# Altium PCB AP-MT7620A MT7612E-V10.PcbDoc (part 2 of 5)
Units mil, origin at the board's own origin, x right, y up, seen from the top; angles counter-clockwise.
Board outline 4645.67 x 3740.16 mil, 4 copper layers (Top, Inner Layer 2, Inner Layer 3, Bottom), stack 35.4 mil thick; 603 components, 409 nets, 1850 pads, 2004 vias.
Unrouted connection lines stored in the file: 90.
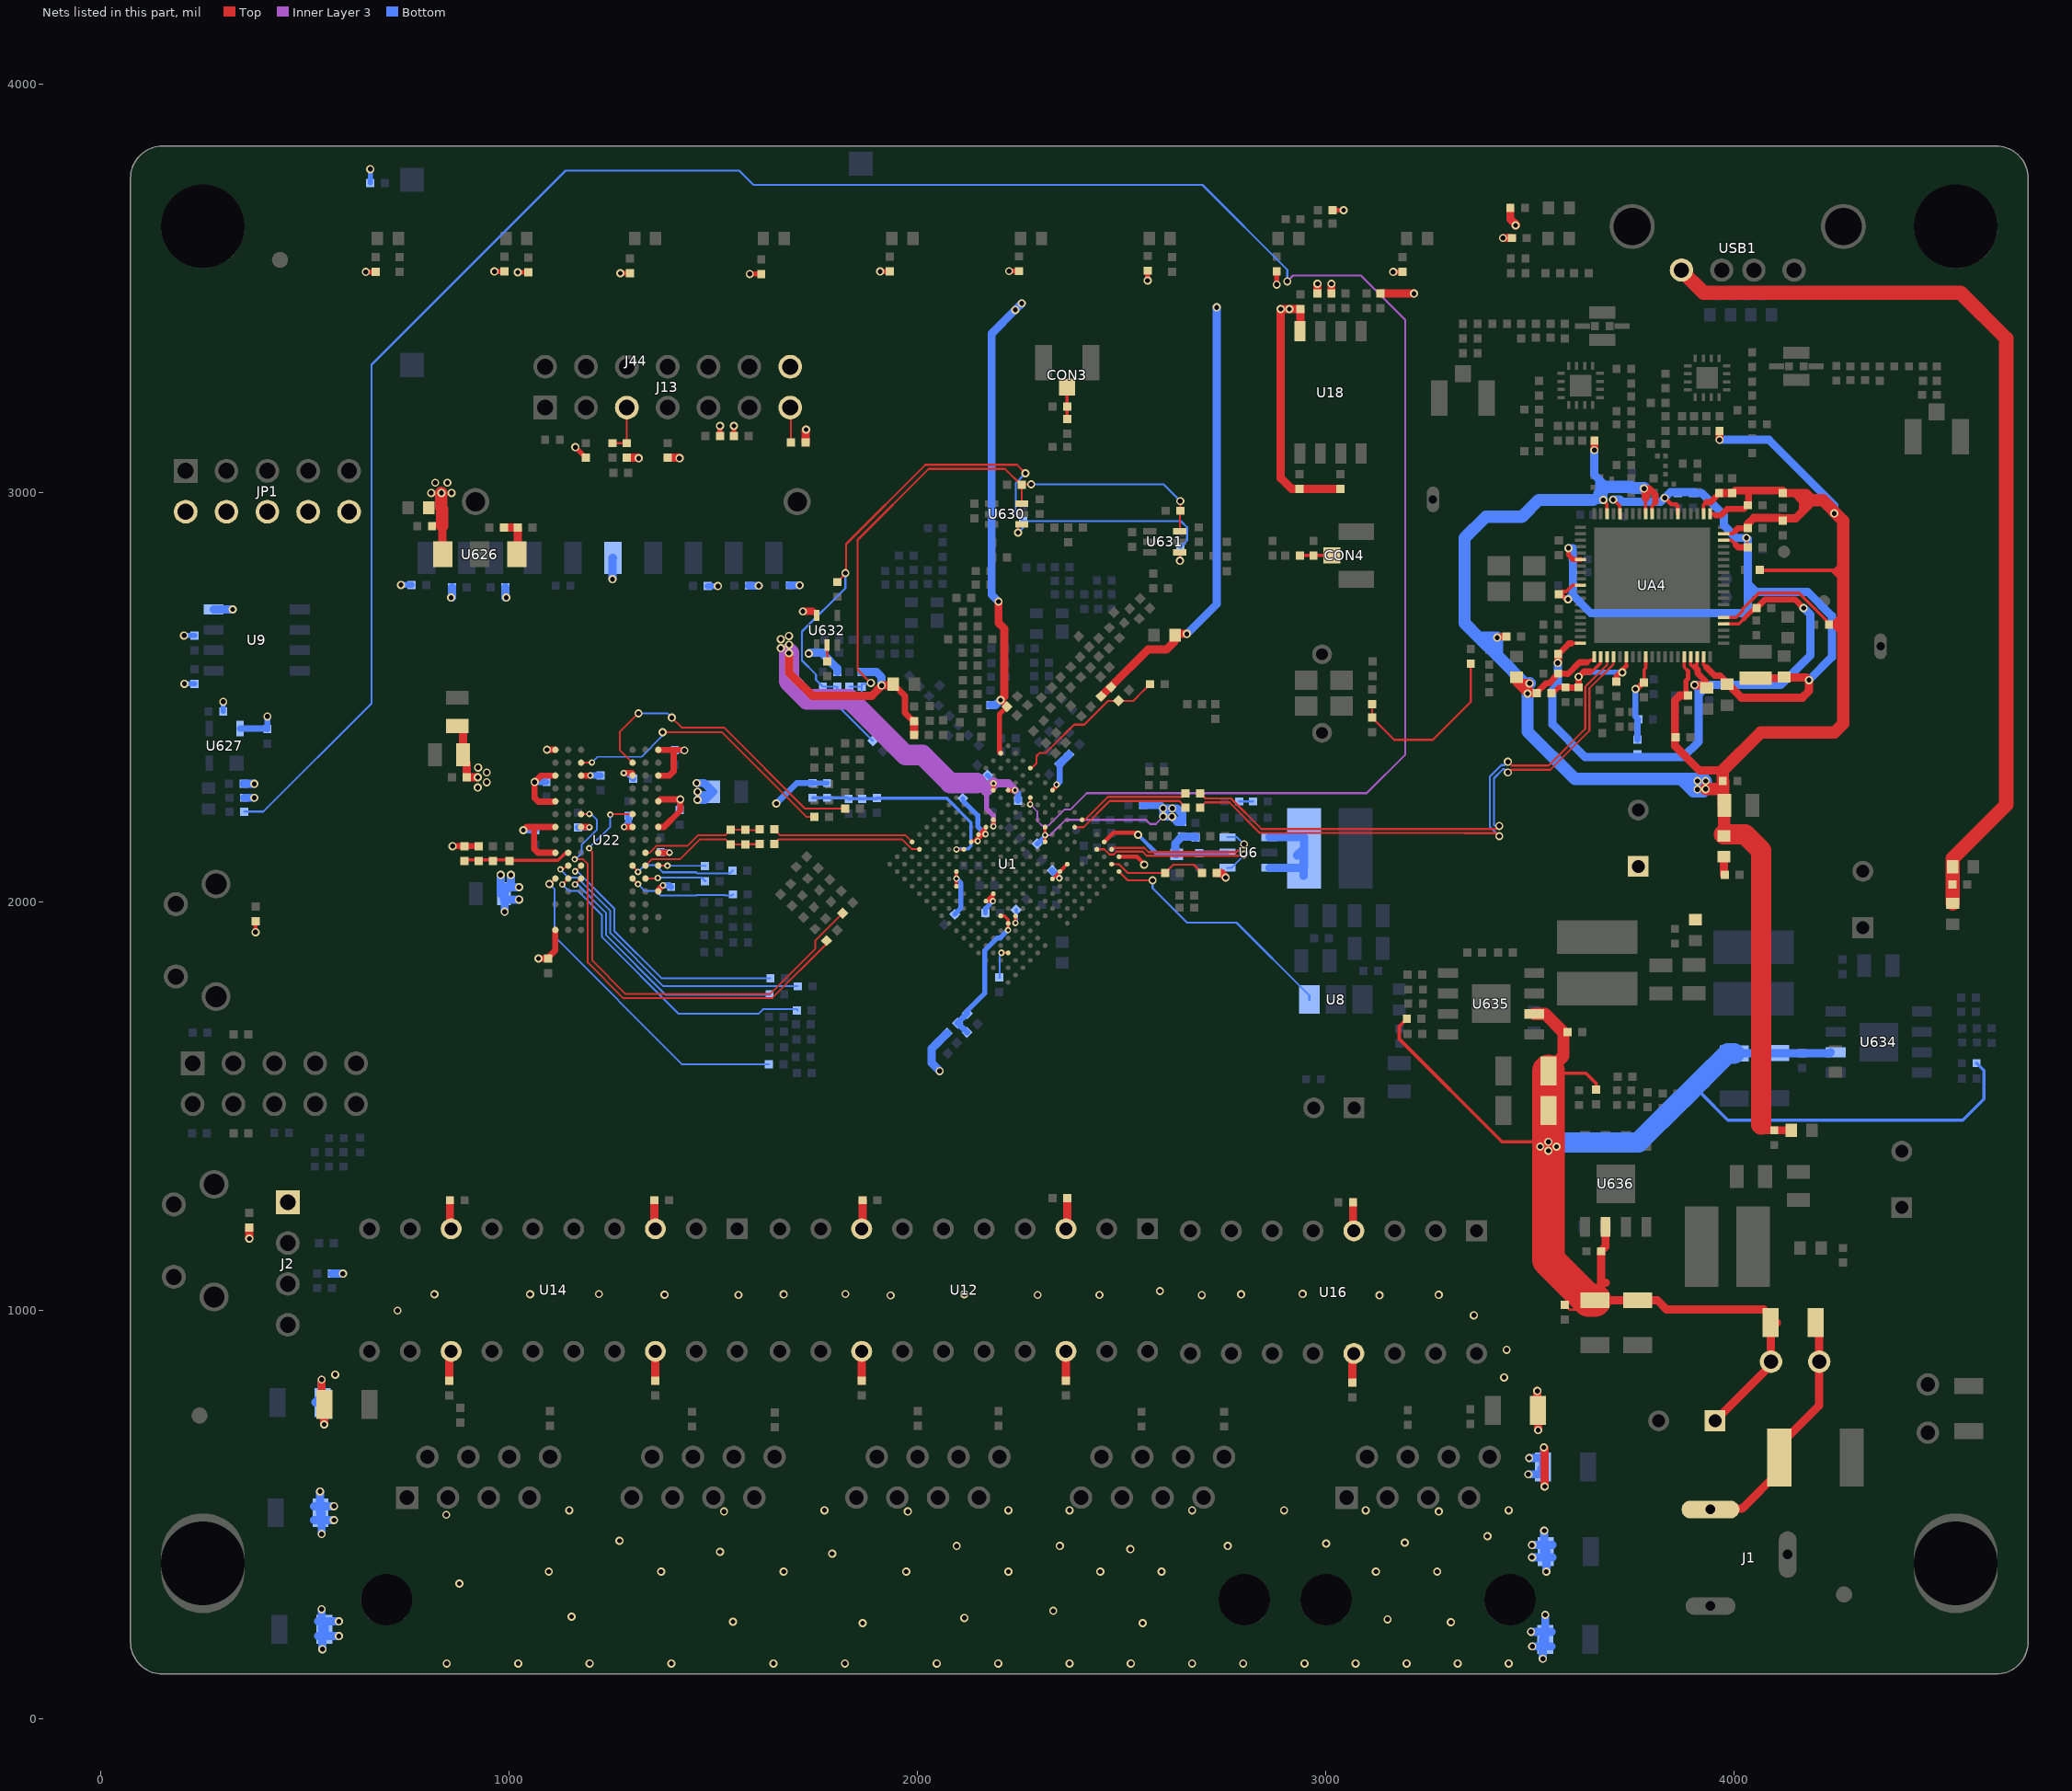
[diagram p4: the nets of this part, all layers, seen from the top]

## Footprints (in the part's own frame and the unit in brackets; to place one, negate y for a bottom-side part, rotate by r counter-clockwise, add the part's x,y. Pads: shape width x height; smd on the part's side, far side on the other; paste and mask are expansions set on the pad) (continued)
SHIELDING$2F$MPCIE$2F$2H$2F$T2 [mil]
  oval 30x62.99 hole 20 slot 53.15 at 90 deg: 1(-547.86,235.76) 2(547.86,-123.96)
  Top region: 220,279.5 220,311 377.48,311 377.48,279.5 220,279.5
  Top region: 405.02,311.02 405.02,279.53 531,279.53 531,-311.02 562.5,-311.02 562.5,311.02 405.02,311.02
  Top region: 273.5,-310.5 273.5,-279 430.98,-279 430.98,-310.5 273.5,-310.5
  Top region: -376,279.5 -376,311 -257.48,311 -257.48,279.5 -376,279.5
  Top region: -404.53,311.02 -562.99,311.02 -562.99,-310.04 -531.5,-310.04 -531.5,279.53 -404.53,279.53 -404.53,311.02
  Top region: -408,-311 -408,-279.5 -250.52,-279.5 -250.52,-311 -408,-311
SKY85601 [mm]
  rect 0.2x0.475 smd mask+0.05: 1(-0.75,-1.212) 2(-0.25,-1.212) 3(0.25,-1.212) 4(0.75,-1.212) 9(0.75,1.212) 10(0.25,1.212) 11(-0.25,1.212) 12(-0.75,1.212)
  rect 0.475x0.2 smd mask+0.05: 5(1.212,-0.75) 6(1.212,-0.25) 7(1.212,0.25) 8(1.212,0.75) 13(-1.212,0.75) 14(-1.212,0.25) 15(-1.212,-0.25) 16(-1.212,-0.75)
  rect 1.35x1.35 smd mask-0.05: 17(0,0)
  silkscreen extent -1.58,-1.58 1.33,1.33
SOIC8$2F$SMD$2F$P1.27$2F$AT24C04B-08B [mm]
  rect 0.61x1.235 smd: 1(-1.905,-2.68) 2(-0.635,-2.68) 3(0.635,-2.68) 4(1.905,-2.68) 5(1.905,2.68) 6(0.635,2.68) 7(-0.635,2.68) 8(-1.905,2.68)
  silkscreen extent -2.97,-2.49 2.5,2
SOIC8$2F$SMD$2F$P1.27$2F$AT26DF321 [mm]
  rect 0.68x1.25 smd: 1(-1.905,-3.805) 2(-0.635,-3.805) 3(0.635,-3.805) 4(1.905,-3.805) 5(1.905,3.805) 6(0.635,3.805) 7(-0.635,3.805) 8(-1.905,3.805)
  silkscreen extent -3.13,-3.17 2.73,2.75
SOP8$2F$SMD$2F$P1.27$2F$IT7653 [mm]
  rect 0.62x1.235 smd: 1(-1.905,-2.682) 2(-0.635,-2.682) 3(0.635,-2.682) 4(1.905,-2.682) 5(1.905,2.682) 6(0.635,2.682) 7(-0.635,2.682) 8(-1.905,2.682)
  rect 2.41x2.41 smd: 9(0,0)
  Top region: -1.65,1.205 1.65,1.205 1.65,-1.205 -1.65,-1.205 -1.65,1.205
  silkscreen extent -2.85,-2.38 2.5,2
SOT89$2F$SMD [mil]
  rect 50x70 smd: 1(-65,0) 2(0,0) 3(65,0)
  Top region: 25,-35 25,50 50,75 50,150 35,165 -35,165 -50,150 -50,75 -25,50 -25,-35 25,-35
  silkscreen extent -100,-45 100,175
SOT223-3$2F$SMD$2F$P2.3$2F$AX1007 [mm]
  rect 1.2x1.6 smd: 1(-2.3,-3.2) 2(0,-3.2) 3(2.3,-3.2)
  Top region: -1.65,4.15 1.65,4.15 1.65,2.25 -1.65,2.25 -1.65,4.15
  silkscreen extent -3.65,-2.15 3.4,1.9
SOT-23-6$2F$SMD$2F$P0.95$2F$APM2701AC [mm]
  rect 0.5x1 smd: 1(-0.95,-1.3) 2(0,-1.3) 3(0.95,-1.3) 4(0.95,1.3) 5(0,1.3) 6(-0.95,1.3)
  silkscreen extent -1.9,-1.25 1.65,1
SOT-143$2F$SMD$2F$G693 [mm]
  rect 0.89x0.95 smd: 1(-0.76,-1.075)
  rect 0.46x0.95 smd: 2(0.96,-1.075) 3(0.96,1.075) 4(-0.96,1.075)
  silkscreen extent -1.92,-1.1 1.62,0.8
SOT-353 [mm]
  rect 0.35x0.7 smd: 1(-0.65,-0.921) 3(0.65,-0.921) 4(0.65,0.921) 5(-0.65,0.921)
  rect 0.3x0.7 smd: 2(0,-0.921)
  silkscreen extent -1.09,-0.38 1.09,0.71
SW$2F$4P$2F$DIP$2F$TS02-CN-PF [mm]
  round 1.5 hole 1: 1(-2.25,0) 2(2.25,0)
  round 1.8 hole 1.3: 3(-3.5,2.5) 4(3.5,2.5)
  silkscreen extent -3.75,-5.85 3.75,4.05
TP30MIL [mil]
  round 30 smd: 1(0,0)
  silkscreen extent -20,-20 20,20
TRANSFORMER$2F$16P$2F$DIP$2F$HN1674CG [mm]
  rect 1.3x1.3 / inner round 1.3 / far side round 1.3 hole 0.8: 1(-8.9,-3.81)
  round 1.3 hole 0.8: 2(-6.35,-3.81) 3(-3.81,-3.81) 4(-1.27,-3.81) 5(1.27,-3.81) 6(3.81,-3.81) 7(6.35,-3.81) 8(8.9,-3.81) 9(8.9,3.81) 10(6.35,3.81) 11(3.81,3.81) 12(1.27,3.81) 13(-1.27,3.81) 14(-3.81,3.81) 15(-6.35,3.81) 16(-8.9,3.81)
  silkscreen extent -10.82,-5.61 10.2,5
TRANSFORMER$2F$20P$2F$DIP$2F$HN2066CG [mm]
  rect 1.3x1.3 / inner round 1.3 / far side round 1.3 hole 0.8: 1(-11.43,-3.81)
  round 1.3 hole 0.8: 2(-8.89,-3.81) 3(-6.35,-3.81) 4(-3.81,-3.81) 5(-1.27,-3.81) 6(1.27,-3.81) 7(3.81,-3.81) 8(6.35,-3.81) 9(8.89,-3.81) 10(11.43,-3.81) 11(11.43,3.81) 12(8.89,3.81) 13(6.35,3.81) 14(3.81,3.81) 15(1.27,3.81) 16(-1.27,3.81) 17(-3.81,3.81) 18(-6.35,3.81) 19(-8.89,3.81) 20(-11.43,3.81)
  silkscreen extent -13.34,-5.81 12.7,5.1
TSON6$2F$SMD$2F$P0.65$2F$UPG2179TB [mm]
  rect 0.4x0.825 smd: 1(-0.65,-0.937) 2(0,-0.937) 3(0.65,-0.937) 4(0.65,0.937) 5(0,0.937) 6(-0.65,0.937)
  silkscreen extent -1.36,-0.97 1.15,0.72
USB$2F$4P$2F$DIP$2F$ATOM$2F$A [mm]
  round 1.45 hole 0.95: 1(3.5,0) 2(1,0) 3(-1,0) 4(-3.5,0)
  round 2.8 hole 2.3: 5(-6.57,-2.71) 6(6.57,-2.71)
  silkscreen extent -7.3,-13.09 7.3,1.21
VARISTOR$2F$SMD$2F$TVM5B150L103RY [mm]
  rect 1.5x3.6 smd: 1(-2.25,0) 2(2.25,0)
  silkscreen extent -1.35,-1.8 1.35,1.8
WBGA84$2F$SMD$2F$P0.8$2F$W9751G6IB [mm]
  round 0.4 smd: A1(-5.6,-3.2) A2(-5.6,-2.4) A3(-5.6,-1.6) A7(-5.6,1.6) A8(-5.6,2.4) A9(-5.6,3.2) B1(-4.8,-3.2) B2(-4.8,-2.4) B3(-4.8,-1.6) B7(-4.8,1.6) B8(-4.8,2.4) B9(-4.8,3.2) C1(-4,-3.2) C2(-4,-2.4) C3(-4,-1.6) C7(-4,1.6) C8(-4,2.4) C9(-4,3.2) D1(-3.2,-3.2) D2(-3.2,-2.4) D3(-3.2,-1.6) D7(-3.2,1.6) D8(-3.2,2.4) D9(-3.2,3.2) E1(-2.4,-3.2) E2(-2.4,-2.4) E3(-2.4,-1.6) E7(-2.4,1.6) E8(-2.4,2.4) E9(-2.4,3.2) F1(-1.6,-3.2) F2(-1.6,-2.4) F3(-1.6,-1.6) F7(-1.6,1.6) F8(-1.6,2.4) F9(-1.6,3.2) G1(-0.8,-3.2) G2(-0.8,-2.4) G3(-0.8,-1.6) G7(-0.8,1.6) G8(-0.8,2.4) G9(-0.8,3.2) H1(0,-3.2) H2(0,-2.4) H3(0,-1.6) H7(0,1.6) H8(0,2.4) H9(0,3.2) J1(0.8,-3.2) J2(0.8,-2.4) J3(0.8,-1.6) J7(0.8,1.6) J8(0.8,2.4) J9(0.8,3.2) K2(1.6,-2.4) K3(1.6,-1.6) K7(1.6,1.6) K8(1.6,2.4) K9(1.6,3.2) L1(2.4,-3.2) L2(2.4,-2.4) L3(2.4,-1.6) L7(2.4,1.6) L8(2.4,2.4) M2(3.2,-2.4) M3(3.2,-1.6) M7(3.2,1.6) M8(3.2,2.4) M9(3.2,3.2) N1(4,-3.2) N2(4,-2.4) N3(4,-1.6) N7(4,1.6) N8(4,2.4) P2(4.8,-2.4) P3(4.8,-1.6) P7(4.8,1.6) P8(4.8,2.4) P9(4.8,3.2) R1(5.6,-3.2) R2(5.6,-2.4) R3(5.6,-1.6) R7(5.6,1.6) R8(5.6,2.4)
  silkscreen extent -6.85,-5.5 6.85,5.5

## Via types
v1: diameter 20, hole 12, Top to Bottom, 1824 vias
v2: diameter 16, hole 8, Top to Bottom, 180 vias

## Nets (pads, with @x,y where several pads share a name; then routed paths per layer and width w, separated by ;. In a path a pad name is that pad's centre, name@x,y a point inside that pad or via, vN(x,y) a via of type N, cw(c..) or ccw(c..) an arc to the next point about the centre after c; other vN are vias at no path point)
1.8VD: C73.1 C75.1 C76.1 C124.1 C128.1 C129.1 C130.1 C131.1 C132.1 C133.1 C134.1 C135.1 C136.1 C138.1 C139.1 C140.1 C820.1 C965.1 C966.1 R350.1 R812.1 R900.2 U1.H5 U1.J5 U1.K5 U1.N6 U1.P7 U22.A1 U22.A9 U22.C1 U22.C3 U22.C7 U22.C9 U22.E1 U22.E9 U22.G1 U22.G3 U22.G7 U22.G9 U22.J1 U22.J9 U22.M9 U22.R1 | length 2346.9
  Top w8: U1.P7@2095.83,2037.21 U1.N6@2095.83,2073.4 ; U1.K5@2132.02,2145.79 2134.24,2148 2139.12,2148 ; v2(2167,2165) v2@2165.21,2166.79 ; U1.H5@2168.21,2181.98 U1.H5@2165.72,2179.49 ; 2139.12,2148 U1.J5@2150.12,2159 ; 2139.12,2148 v2@2146.42,2148 ; v2@2146.42,2148 v2@2148.77,2150.35 ; v2@2146.42,2148 v2(2148,2148) v2@2148.77,2150.35 ; v2@2148.77,2150.35 v2@2150.12,2151.7 ; v2@2150.12,2151.7 v2@2150.82,2152.39 ; v2@2150.12,2151.7 U1.J5@2150.12,2159 ; U1.J5@2150.12,2159 U1.J5@2150.12,2163.88 2159.12,2172.88 ; v2@2150.82,2152.39 v2@2165.21,2166.79 ; v2@2150.82,2152.39 2150.82,2155.61 v2@2163.61,2168.39 ; 2159.12,2172.88 U1.H5@2165.72,2179.49 ; 2159.12,2172.88 v2@2163.61,2168.39 ; v2@2163.61,2168.39 v2@2165.21,2170 ; v2@2163.61,2168.39 v2@2165.21,2166.79 ; v2@2165.21,2166.79 v2@2165.21,2170 ; v2@2165.21,2170 2165.72,2170.51 U1.H5@2165.72,2179.49
  Top w15: v1(862.5,2135.5) C124.1@891.5,2135.5 R350.1@926.5,2135.5 ; v1(1035.5,2174.5) 1043.31,2182.31 1062.32,2182.31 ; v1(1072.6,1860.56) 1094.01,1860.56 C132.1@1094.07,1860.5 ; v1(1093.5,2371.5) 1113.86,2371.5 U22.A1@1114.07,2371.29 ; C132.1@1096.5,1860.5 C132.1@1094.07,1860.5 ; U22.R1@1114.07,1930.35 1114.07,1880.5 C132.1@1094.07,1860.5 ; U22.J1@1114.07,2119.32 1071.5,2119.32 1062.32,2128.5 1062.32,2182.31 ; U22.G1@1114.07,2182.31 1062.32,2182.31 ; U22.E1@1114.07,2245.31 1113.26,2244.5 1072.5,2244.5 1063.5,2253.5 v1(1063.5,2292.5) 1079.3,2308.3 U22.C1@1114.07,2308.3 ; U22.G3@1177.06,2182.31 1196.69,2182.31 v2(1197.5,2181.5) ; U22.C3@1177.06,2308.3 1199.4,2308.3 v2(1199.7,2308.6) ; v2(1281.5,2314.5) 1301.5,2314.5 1303.05,2312.95 U22.C7@1303.05,2308.3 ; v2(1282.5,2182.5) 1302.86,2182.5 U22.G7@1303.05,2182.31 ; U22.M9@1366.04,2024.83 1366.04,2028.04 v2(1377.5,2039.5) ; U22.J9@1366.04,2119.32 1393.32,2119.32 v2(1393.5,2119.5) ; U22.G9@1366.04,2182.31 1379.95,2182.31 1420,2222.37 v1(1420,2250) 1370.73,2250 U22.E9@1366.04,2245.31 ; U22.C9@1366.04,2308.3 1393.5,2308.3 1403.5,2318.3 1403.5,2371.29 ; U22.A9@1366.04,2370.5 U22.A9@1366.04,2371.29 1403.5,2371.29 ; v1(1430,2370) 1430,2371.29 1403.5,2371.29
  Top w20: R900.2@874,2429.55 888.45,2429.55 C965.1@888.45,2359 888.45,2348 897,2339.45 C966.1@897,2304 v1(924,2304)
  Bottom w12: R812.1@1744,2290 C820.1@1779,2290 ; C76.1@2091.73,1968.73 2107,1984 2107,2045 v2(2096,2056) ; C75.1@2111.73,2252.27 2111.73,2247 2148,2211 2148,2184 v2(2167,2165)
  Bottom w15: v1(1035.5,2174.5) C129.1@1064.5,2174.5 ; v1(1063.5,2292.5) C138.1@1092.5,2292.5 ; C131.1@1169.5,2181.5 v2(1197.5,2181.5) ; v2(1199.7,2308.6) 1224.4,2308.6 C140.1@1224.5,2308.5 ; v2(1281.5,2314.5) 1290.5,2314.5 C128.1@1304.5,2300.5 ; v2(1282.5,2182.5) 1293.5,2193.5 C133.1@1293.5,2209.5 ; C139.1@1371.5,2120.5 1392.5,2120.5 v2(1393.5,2119.5) ; v2(1377.5,2039.5) 1393.5,2039.5 C130.1@1397.5,2035.5 ; C134.1@1406.5,2370.5 1406.5,2370 v1(1430,2370) ; C135.1@1418.5,2224.5 1420,2224.5 v1(1420,2250) ; C136.1@1500.05,2268.5 C136.1@1500.5,2268.05 ; v1(1655,2240) 1705,2290 R812.1@1744,2290
  Bottom w20: v1(980,2065) 980,2019 C73.1@988.45,2019 ; v1(990,1975) C73.1@990,2005 ; v1(1005,2065) 1005,2040 C73.1@1000,2035 ; v1(1025,2005) C73.1@990,2005 ; v1(1025,2035) C73.1@1000,2035 ; v1(1460,2290) 1478.55,2290 C136.1@1500.05,2268.5 C136.1@1500,2268.5 ; v1(1461.87,2248.71) 1480.21,2248.71 C136.1@1500,2268.5 ; v1(1462.24,2268.71) 1462.24,2268.27 1470.51,2260 1490,2260 1498.5,2268.5 C136.1@1500,2268.5 ; C73.1@988.45,2019 988.45,2005 C73.1@990,2005 ; C73.1@988.45,2019 990,2019 C73.1@990,2005 ; C73.1@988.45,2019 C73.1@988.45,2023.45 ; C73.1@988.45,2023.45 C73.1@1000,2035 ; C73.1@988.45,2023.45 988.45,2035 C73.1@1000,2035
  other v1: 924,2279 946,2292 946,2316 925,2328
3.3V: C925.1 C926.1 C952.1 CA41.1 CA42.1 CA43.1 CA45.1 CA52.1 CA53.1 CA55.1 CA56.1 CA57.1 CA58.1 CA63.1 CA64.1 CA74.1 L645.2 L648.2 R162.1 R164.1 RA7.2 RA10.1 RA18.2 RA21.2 UA4.20 UA4.34 UA4.43 UA4.56 UA4.58 UA4.59 UA4.67 UA4.68 UA4.74 | length 6771.4
  Top w5: CA64.1@3855,2402 CA64.1@3857,2402 ; RA21.2@4232,2678 4247,2678
  Top w8: 3639.38,2585.51 3642.04,2585.51 3646.94,2590.41 3657.27,2590.41 UA4.20@3657.27,2598.8 ; v1(3679.62,2982.87) 3678.86,2982.12 3688.76,2972.22 3688.76,2958.65 UA4.74@3688.76,2949.2 ; UA4.68@3783.25,2949.2 3783.25,2983.28 3783.37,2983.4 3783.37,2988.13 ; UA4.67@3799,2949.2 3799,2968.16 3807.14,2976.3 ; UA4.34@3877.74,2598.8 3877.74,2573.31 3886.86,2564.19 ; UA4.59@3924.98,2949.2 3924.98,2970.63 3931.71,2977.36 ; UA4.58@3940.73,2949.2 3949.34,2949.2 3953.75,2944.79 ; UA4.43@3974.2,2695.26 4004.74,2695.26 4020.71,2711.23 4020.71,2715.27 4060.37,2754.93 4158.88,2754.93 4232,2681.82 RA21.2@4232,2678 ; UA4.56@3974.2,2899.98 3974.2,2900.57 3996.19,2900.57 4003.03,2907.41
  Top w10: RA10.1@4062.88,2812 4062.88,2810.68 4240,2810.68 ; 4267,2783.68 4240,2810.68 ; 4267,2810 4266.32,2810.68 4246.33,2810.68 ; 4267,2831.35 4246.33,2810.68 ; 4240,2810.68 4246.33,2810.68
  Top w12: CA63.1@3882,2504 3882,2540.55 3886.86,2545.41 3886.86,2564.19
  Top w15: RA18.2@3517,2511.68 3539.32,2534 3546.68,2534 3558.2,2545.52 3558.2,2546.91 3567.24,2555.95 3567.24,2558 CA74.1@3569,2558 3586.79,2558 3590.33,2556.53 3592.7,2556.53 3621.68,2585.51 3639.38,2585.51 ; 3803,3000 3807.14,2995.86 3807.14,2976.3 ; 3931.71,2977.36 3942.05,2977.36 3963.84,2999.16 CA53.1@3963.84,3000 ; 3953.75,2944.79 3966.56,2944.79 3982.34,2960.57 4023.57,2960.57 CA56.1@4033,2970 ; 4003.03,2907.41 4009.62,2914 CA58.1@4033,2914
  Top w16: v1(3420,2646) 3420,2647.98 3442.69,2647.98 RA7.2@3442.69,2648.48 ; v1(3499,2534) 3499,2516 3503,2512 3517,2512 3517,2511.68 RA18.2@3517,2510 ; v1(3779.26,3010.78) 3792.22,3010.78 3803,3000 ; CA56.1@4033,2970 4035,2970 4035,3006 ; CA57.1@4115,2936 CA57.1@4115,2938
  Top w20: v1(3499,2534) 3498.29,2534.71 3480.7,2534.71 CA43.1@3467,2548.41 3467,2536 v1(3494,2509) 3494,2510 RA18.2@3517,2510 ; v1(3657.64,3105.03) 3658,3105.03 R162.1@3658,3128 ; v1(3779.26,3010.78) 3783.37,3006.66 3783.37,2988.13 ; CA63.1@3887,2504 3882,2504 3867,2504 3855,2492 3855,2402 3855,2381 3915,2321 3972,2321 ; CA53.1@3963,3000 3963.84,3000 CA52.1@3995,3000 3997,3000 4003,3006 4035,3006 4119,3006 CA55.1@4119,3000 4148.36,3000 ; R164.1@3964,3152 3964,3129.95 v1(3964.08,3129.95) ; CA58.1@4033,2914 4033,2924 4048,2939 4112,2939 4115,2936 CA57.1@4119,2932 ; 4066,1454 4076,1444 4076,1440 C952.1@4098,1440 L648.2@4139.41,1440 ; CA57.1@4115,2938 4151,2938 4168,2955 ; 4175,2980 4175,2962 ; 4267,2658 4247,2678 4267,2698 ; 4148.36,3000 4168,2980.36 4168,2955 ; 4148.36,3000 4177,3000 4195,2982 4175,2962 ; 4168,2955 4175,2962
  Top w30: v1(3930,2275) 3972,2275 3973.55,2275 ; L645.2@3975,2160.59 3975.55,2160.59 3975.55,2164.42 C925.1@3975.55,2235 3973.55,2235 3973.55,2275 ; 4175,2980 4175,2982 4195,2982 4217.05,2982 4267,2932.05 4267,2831.35 4267,2810 4267,2783.68 4267,2698 4267,2658 4267,2435.24 4245.76,2414 4065,2414 3972,2321 C926.1@3972,2295 3973.55,2295 3973.55,2275
  Top w50: L645.2@3975.55,2164.42 4026.91,2164.42 4066,2125.33 4066,1454
  Bottom w20: v1(3657.64,3105.03) 3657.64,3044.36 3670,3032 ; v1(3679.62,2982.87) v1@3679.62,2983 ; 3679.62,3007.62 v1@3679.62,2983 ; 3687,3015 3670,3032 ; v1(3964.08,3129.95) 4085.05,3129.95 4245,2970 v1(4245,2950) ; 3670,3032 3670,2998 CA42.1@3655,2983 v1@3679.62,2983
  Bottom w30: v1(3499,2534) v1@3494,2529 ; CA42.1@3655,2983 CA41.1@3623,2983 3521.65,2983 3480.65,2942 3392,2942 3339.88,2889.88 3339.88,2681.69 3375.57,2646 ; 3670,2998 3679.62,3007.62 3687,3015 3747,3015 CA45.1@3750,3012 3779.26,3012 v1(3779.26,3010.78) ; 3375.57,2646 v1(3420,2646) 3420,2601.57 ; 3375.57,2646 3420,2601.57 ; 3420,2601.57 3492.57,2529 v1@3494,2529 ; v1@3494,2529 v1(3494,2509) 3494,2416 3610,2300 3872.28,2300 ; 3872.28,2300 3872.28,2297.56 3899.86,2269.98 3910.21,2269.98 3924.98,2269.98 v1(3930,2275) ; 3872.28,2300 v1@3905,2300 ; v1@3905,2300 v1(3930,2275) ; v1@3905,2300 3925.29,2300 v1(3930.29,2295) 3930,2294.71 v1(3930,2275)
  other v1: 3910,2274.51 3910.21,2294.98
3.3VD: C39.1 C40.1 C41.1 C91.1 C92.2 C93.1 C109.2 C110.1 C137.1 C215.1 C456.1 C457.1 C928.1 C963.1 C964.1 C969.1 C1033.1 D47.2 J2.1 J13.14 J44.4 JP1.2 JP1.4 JP1.6 JP1.8 JP1.10 L13.1 L14.1 L644.2 L645.1 R27.1 R28.1 R29.1 R52.1 R53.1 R124.1 R125.1 R128.1 R129.1 R132.1 R133.1 R136.1 R137.1 R151.2 R154.1 R155.2 R156.2 R158.2 R160.2 R163.2 R165.2 R166.2 R167.2 R170.2 R355.1 R370.2 R371.1 R372.2 R373.1 R374.2 R375.1 R376.1 R377.1 R388.1 R389.1 R471.1 R472.1 R473.1 R474.1 R475.1 R476.1 R896.1 R897.1 R912.2 R923.2 SR2.1 U1.A16 U1.B1 U1.D4 U1.D9 U1.E3 U1.E10 U1.E13 U1.F13 U1.G5 U1.G13 U1.M10 U1.N10 U9.8 U18.8 U626.3 U627.4 U632.5 | length 7076.7
  Top w8: U1.N10@2168.21,2001.02 2176.6,2009.4 ; U1.N10@2168.21,2001.02 v2(2185,2001) ; U1.M10@2186.31,2019.12 U1.M10@2185,2017.81 ; U1.E10@2312.98,2145.79 U1.D9@2312.98,2181.98 ; U1.G13@2331.07,2055.31 2339.38,2063.62 ; v2(2348,2057) 2341.38,2063.62 2339.38,2063.62 ; U1.E13@2367.26,2091.5 U1.F13@2349.17,2073.4 2339.38,2063.62 ; 2176.6,2009.4 U1.M10@2185,2017.81 ; 2176.6,2009.4 v2(2185,2001) ; v2(2185,2001) U1.M10@2185,2017.81
  Top w10: v1(380,1925) R154.1@380,1952 ; 1743.69,2710 U632.5@1753.41,2700.28 ; U1.G5@2186.31,2200.07 v2(2186.4,2184) ; U1.E3@2186.31,2272.45 2186.31,2289 v2(2186.5,2289) ; U1.D4@2222.5,2272.45 v2(2239.3,2272.5) v2(2239.3,2272.5) ; U1.A16@2493.93,2109.6 2538.08,2109.6 2556.55,2091.12 v1(2555.55,2090.11)
  Top w12: v1(650,3541) R158.2@674,3541 ; v1(965,3542) R374.2@989,3542 ; v1(1022,3540) R136.1@1048,3540 ; v1(1163,3112) R476.1@1189,3086 ; v1(1273,3538) R167.2@1297,3538 ; R473.1@1517,3139 v1(1517,3164) ; R472.1@1551,3139 v1(1551,3164) ; v1(1590,3536) R166.2@1618,3536 ; v1(1909,3542) R165.2@1933,3542 ; U1.B1@2204.4,2362.93 2201,2366.33 2201,2458 C110.1@2219.77,2476.77 ; v1(2225,3543) R163.2@2249,3543 ; v1(2564,3520) R160.2@2564,3544 ; v1(2880,3510) R155.2@2880,3542 R155.2@2880,3547 ; R132.1@3017,3692 v1(3044,3692) ; v1(3165,3541) R372.2@3188,3541
  Top w15: C457.1@1941.41,2532 1970,2503.41 1970,2461.5 C109.2@1992.5,2439 ; v1(2204,2493) 2204,2492.54 C110.1@2219.77,2476.77
  Top w18: v1(1720,2710) 1743.69,2710
  Top w20: v1(365,1175) R355.1@365,1202 ; 837,2919 837,2849.98 U626.3@838.45,2849.98 ; R475.1@1289,3086 1317,3086 v1(1318,3085) ; R474.1@1389,3086 1417,3086 v1(1418,3085) ; v1(1686,2608) 1686,2560.36 1742.7,2503.66 1888.81,2503.66 1913.48,2528.34 v1(1912.91,2528.91) 1941.41,2528.91 C457.1@1941.41,2532 ; R471.1@1727,3124 1727,3154 v1(1728,3155) ; L13.1@1992.5,2407.5 1992.5,2439 C109.2@1992.5,2441.5 ; v1(2199,2734) 2199,2681.93 2213.07,2667.86 2213.07,2502.07 v1(2204,2493) ; L14.1@2450.23,2502.23 C92.2@2472.77,2524.77 ; C92.2@2474.23,2524.77 C92.2@2472.77,2524.77 ; v1(2660,2655) 2631.09,2655 C456.1@2631.09,2652 2631.09,2638 2610,2616.91 2564.91,2616.91 C92.2@2472.77,2524.77 ; R28.1@2733,2070 2743.76,2070 v1(2755,2058.76) ; v1(2890,3450) v1@2890,3448 ; U18.8@2937,3395.8 2938,3395.8 C137.1@2938,3450 v1(2911,3450) 2892,3450 v1@2890,3448 ; R151.2@2980,3488 v1(2980,3512) ; R125.1@3014,3488 v1(3014,3512) ; SR2.1@3036,3010 R170.2@2936,3010 2916,3010 2890,3036 v1@2890,3448 ; R133.1@3134,3488 v1(3216,3488) ; v1(3434,3624) R370.2@3456,3624 ; R156.2@3452,3698 3452,3670.28 3466.14,3656.14 v1(3465,3655) ; L645.1@3975,2109.41 3975,2065 C928.1@3977,2065
  Top w30: v1(835,3000) 834.59,3000 834.59,2964 837,2961.59 837,2919
  Inner Layer 3 w5: v2(2313,2162.5) 2325.76,2162.5 2363.26,2200 2560,2200 2570,2190 2584.21,2190 v1(2602.27,2208.06)
  Inner Layer 3 w12: 2145,2290 2170,2265 ; 2170,2272.5 2170,2265 ; v2(2186.4,2184) 2186.4,2210 2170,2226.4 2170,2265
  Inner Layer 3 w20: v2(2186.5,2289) 2222.8,2289 v2(2239.3,2272.5)
  Inner Layer 3 w30: 2170,2272.5 v2(2186.5,2289)
  Inner Layer 3 w50: v1(1686,2608) 1686,2539 1730,2495 1835,2495 1971.36,2358.64 2012.36,2358.64 2081,2290 2145,2290
  Bottom w12: v1(205,2651) R53.1@231,2651 ; v1(206,2533) R52.1@231,2533 ; R896.1@301,2465 v1(301,2489) ; R389.1@661,3758.5 v1(661,3792.5) ; C41.1@2167,1972 2167,1982 2166.5,1982.5 v2(2185,2001) ; C93.1@2172.23,2308.77 2186.5,2294.5 v2(2186.5,2289) ; C40.1@2293.85,2141.11 2313,2160.26 v2(2313,2162.5)
  Bottom w15: U627.4@341.8,2423.32 407.68,2423.32 C969.1@409,2422 v1(409,2453) ; v1(736,2775) R388.1@762,2775 ; R377.1@1487,2772 v1(1512,2772) ; v2(2239.3,2272.5) 2247,2264.8 C91.1@2247,2247 ; C39.1@2330.23,2075.77 2348,2058 v2(2348,2057)
  Bottom w20: U9.8@277.49,2715 v1(324,2715) ; R897.1@351,2288 v1(377,2288) ; D47.2@352,2254 v1(377,2254) ; R137.1@567,1089 v1(594,1089) ; v1(859,2744) 861,2744 R375.1@861,2769 ; R376.1@992,2769 992,2744 v1(994,2744) ; v1(1254,2789) 1254,2841 J44.4@1255.3,2841 ; R373.1@1588,2773 v1(1612,2773) ; R371.1@1688,2774 v1(1712,2774) ; v1(1734.38,2606.95) 1736.43,2609 R912.2@1773,2609 1773,2601.5 1804,2570.5 R129.1@1804,2562 ; R128.1@1864,2562 1899.82,2562 1912.91,2548.91 v1(1912.91,2528.91) ; v1(2055,1585) 2035.51,1604.49 2035.51,1640.23 2049.14,1653.86 C215.1@2049.27,1653.73 2049.73,1653.73 R29.1@2073.27,1677.27 ; R923.2@2179.5,2480.5 2191.5,2480.5 v1(2204,2493) ; v1(2199,2734) 2182,2751 2182,3390 v1(2240,3448) v1(2256,3464) ; R124.1@2553,2236 2594.06,2236 v1(2602,2228.06) v1@2602.14,2228.06 ; v1(2660,2655) 2733.21,2728.21 v1(2733.21,3454.28) ; v1@2602.14,2228.06 2635.44,2228.06 2648.5,2215 R27.1@2648.5,2195 2636.38,2195 v1(2623.73,2207.64) 2623.73,2207.85 2602.27,2207.85 v1(2602.27,2208.06) 2602.14,2208.06 v1@2602.14,2228.06
  other v1: 2624.52,2228.02 1666,2620 1686.39,2628.61 1666,2642 1686,2650 810,3000 860,3000 820,3025 850,3025
5V_USB: C967.1 C968.1 R895.2 USB1.1 | length 2367.5
  Top w20: C968.1@4534,2042 4534.41,2042.41 C967.1@4534.41,2085
  Top w30: C967.1@4533.82,2084.41 C967.1@4534.41,2085
  Top w35: USB1.1@3870.97,3545.58 3871.24,3545.62 3870.31,3544.69 3925,3490 4554,3490 4666,3378 4666,2236.59 4534.41,2105 ; C967.1@4534.41,2085 4534.41,2105 ; R895.2@4535,1995.59 4535,2085 4535,2104.41 4534.41,2105
12V: C1.1 C2.1 C1016.1 C1017.1 C1018.2 C1025.1 C1026.1 C1028.2 C1037.1 C1038.1 C1039.2 L35.2 R255.2 R940.1 R942.1 R948.1 U634.2 U635.2 U636.2 | length 4206.5
  Top w5: C2.1@3585,1013 3596.77,1001.23 3620.37,1001.23 C1038.1@3643.25,1024.12
  Top w8: R942.1@3198.5,1713 3180,1694.5 3180,1663.42 3431.42,1412 v1(3545,1412) v1(3545,1390) ; 3572.54,1581.69 3585,1580 3637,1580 3662,1555 R948.1@3662,1540
  Top w20: C1038.1@3659,1024.12 C1037.1@3764,1024.12 3811.88,1024.12 3834,1002 4071.63,1002 4104.63,969 R255.2@4089.94,969 ; U636.2@3685,1203.39 U636.2@3685,1190.89 ; 3685.63,1067.12 3674,1067.12 C1039.2@3674,1144 3685,1155 U636.2@3685,1190.89 ; U636.2@3686,1189.89 U636.2@3685,1190.89 ; C1.1@3952.9,729 4089.94,866.05 L35.2@4089.94,874 R255.2@4089.94,969 ; R255.2@4088.88,969 R255.2@4089.94,969
  Top w30: U635.2@3510.61,1725 3537,1725 3582,1680 3582,1621.88 C1025.1@3545.12,1585
  Top w80: C1025.1@3545.12,1585 C1026.1@3545.12,1489 3545.12,1390 v1(3545,1390) 3545,1122.37 3643.25,1024.12 C1038.1@3659,1024.12
  Bottom w8: 3920,1563.87 3920,1529.54 3984.54,1465 4560,1465 4611.5,1516.5 4611.5,1586.5 R940.1@4593.5,1604.5
  Bottom w20: v1(3525,1400) 3530,1395 3530.29,1395.33 3534.09,1399.63 v1(3545,1412) v1(3545,1390) ; 3555,1410 v1(3565,1400) ; C1016.1@4000,1628.12 4000.88,1629 C1017.1@4099.12,1629 ; C1017.1@4099,1629.12 C1017.1@4099.12,1629 ; U634.2@4235.89,1631 4233.89,1629 C1018.2@4166,1629 C1017.1@4099.12,1629
  Bottom w50: v1(3545,1412) 3549.23,1411.15 3555,1410 3765,1410 3870,1515 3871.13,1515 3920,1563.87 3984.25,1628.12 C1016.1@4000,1628.12
12V_L: D1.2 J1.3 L35.1 R255.1 | length 620.1
  Top w20: J1.3@3942,512 3944,514 4019,514 4110.42,605.42 D1.2@4110.42,639 4110.42,669 4208.06,766.64 L35.1@4208.06,874 4208.06,969 R255.1@4199.12,969
AA: C31.2 R22.1 | length 34
  Bottom w5: R22.1@2788,2245 C31.2@2822,2245
ANT_TRN: C990.1 C1007.1 R128.2 R130.2 R952.2 U630.6 U631.6 | length 1584.9
  Top w5: v1(1886.24,2535.04) 1854,2567.28 1854,2885 2028,3059 2215,3059 2254,3020 C990.1@2256,3020 ; U630.6@2255.91,2974.09 2255.91,3019.91 C990.1@2256,3020 ; v1(2279,3021) 2256,3021 C990.1@2256,3020 ; U631.6@2642.91,2906.09 2642.91,2956.5 C1007.1@2644.5,2956.5 2644.5,2979.5 v1(2644,2980)
  Bottom w5: R130.2@1834,2526 R128.2@1864,2526 ; v1(1886.24,2535.04) 1886.24,2532.78 1864,2532.78 R128.2@1864,2526 ; R952.2@1916.27,2414.73 1900,2414.73 1864,2450.73 R128.2@1864,2526 ; v1(2279,3021) 2603,3021 v1(2644,2980)
ANT_TRNB: C992.1 C1008.1 R129.2 R131.2 R953.2 R954.1 U630.4 U631.4 | length 1892.7
  Top w5: R954.1@1804,2782 v1@1826,2804 ; v1(1824,2804) v1@1826,2804 ; v1(2247,2903) 2247,2922.91 U630.4@2255.91,2922.91 ; v1(2265,3048) 2244,3069.01 2020.01,3069.01 1826,2875 v1@1826,2804 ; U631.4@2642.91,2854.91 2643,2854.82 v1(2643,2834)
  Bottom w5: v1(1824,2804) 1824,2766.8 1717.88,2660.67 1717.88,2589.79 1752.32,2555.35 1752.32,2542.68 R131.2@1769,2526 R129.2@1804,2526 1804,2481 R953.2@1891.27,2393.73 ; v1(2247,2903) 2259,2915 C992.1@2259,2931 ; v1(2265,3048) 2241,3024 2241,2949 C992.1@2259,2931 ; v1(2643,2834) 2644,2835 C1008.1@2644,2867 2660.5,2883.5 2660.5,2915.69 2645.19,2931 C992.1@2259,2931
ANTENNA_0: C970.1 CON4.1 L601.1 | length 78
  Top w8: L601.1@2937,2847 C970.1@2970,2847 CON4.1@3014.96,2847
ANTENNA_1: C991.1 CON3.1 L600.1 | length 78
  Top w8: L600.1@2367,3181 C991.1@2367,3211 CON3.1@2367,3258.96
APCK_RFCKO_N: R382.2 UA4.22 | length 1414.6
  Top w5: R382.2@2693,2230 2705.5,2242.5 2763.96,2242.5 2838.92,2167.54 3340.11,2167.54 3340.15,2167.5 3417.5,2167.5 v1(3425,2160) ; v1(3446,2342) 3455.13,2332.87 3545.86,2332.87 3635.5,2422.51 3635.5,2526.06 3688.76,2579.32 UA4.22@3688.76,2598.8
  Bottom w5: v1(3425,2160) 3402,2183 3402,2306 3430,2334 3438,2334 v1(3446,2342)
APCK_RFCKO_P: R383.2 UA4.23 | length 1393.2
  Top w5: R383.2@2693,2265 2705.5,2252.5 2768.1,2252.5 2843.06,2177.54 3417.54,2177.54 v1(3425,2185) ; v1(3446,2316) 3452.87,2322.87 3550,2322.87 3645.5,2418.37 3645.5,2521.91 3704.51,2580.93 UA4.23@3704.51,2598.8
  Bottom w5: v1(3425,2185) 3414.14,2185 3412,2187.14 3412,2301.86 3434.14,2324 3438,2324 v1(3446,2316)
APCK_RFCKON: R382.1 U1.B11 | length 308.4
  Top w5: U1.B11@2385.36,2181.98 2406.98,2181.98 2471,2246 2641.87,2246 2651.63,2236.24 2657,2236.24 R382.1@2657,2230
APCK_RFCKOP: R383.1 U1.A11 | length 284.2
  Top w5: U1.A11@2403.45,2200.07 2403.45,2201 2411.86,2201 2466.86,2256 2648.13,2256 2651.63,2259.5 2657,2259.5 R383.1@2657,2265
AVDD15_CLDO_IN: CA34.1 CA35.1 CA44.1 CA47.1 CA48.1 CA49.1 CA51.1 CA54.1 CA59.1 CA60.1 LA16.2 RA20.2 UA4.6 UA4.10 UA4.37 UA4.55 UA4.63 UA4.72 | length 2446.5
  Top w5: v1(4030,2890) 4032.3,2887.7 CA49.1@4032.3,2867 ; CA47.1@4120,2548 4120,2549.41 CA47.1@4122,2549.41
  Top w8: CA44.1@3571,2752 3573.39,2754.39 3577.84,2758.84 3589.35,2758.84 3604.51,2774 UA4.10@3623.8,2774 ; v1(3703.65,2983.49) 3703.65,2984.57 3704.19,2984.03 3720.26,2967.95 UA4.72@3720.26,2949.2 ; UA4.37@3924.98,2598.8 3924.98,2580.02 3932,2573 ; UA4.55@3974.2,2884.24 3992.82,2884.24 4004.14,2872.91
  Top w10: v1(3830,2988) 3846,2972 3857.97,2972 3861.99,2967.98 UA4.63@3861.99,2949.2
  Top w12: CA44.1@3571,2752 3573.39,2752 3573.39,2754.39 3590.62,2737.15 v1(3593.16,2739.68) ; v1(3594.33,2865.07) 3594.33,2848.32 3603.5,2839.15 3603.5,2837.52 3604.02,2836.99 UA4.6@3623.8,2836.99
  Top w15: 3932,2573 3952.04,2552.96 3965.84,2552.96 3984.11,2534.7 3983,2534.7 CA60.1@3983,2531.59 ; 4004.14,2872.91 4010.05,2867 4032.3,2867 CA49.1@4033,2867
  Top w20: CA60.1@3983,2531.59 3985,2531.59 4017.59,2499 4167,2499 4183,2515 v1(4183,2542) 4177,2548 CA47.1@4120,2548 ; LA16.2@4053,2546.52 4120,2546.52 CA47.1@4120,2548 ; CA47.1@4122,2549.41 CA47.1@4120,2548
  Bottom w5: CA51.1@3862,3000 CA51.1@3862,3002
  Bottom w16: CA59.1@3899,3000 CA59.1@3901,3002
  Bottom w20: v1(3593.16,2739.68) 3603.48,2750 3605,2750 ; v1(3594.33,2865.07) 3604.33,2865.07 3604.33,2838 CA35.1@3605,2838 CA34.1@3605,2806 RA20.2@3605,2774 3605,2750 ; v1(3703.65,2983.49) 3703.65,2984.57 3719.43,2984.57 3726,2978 CA54.1@3728,2978 3819.77,2978 v1@3830,2988.23 ; v1(3830,2988) v1@3830,2988.23 ; CA59.1@3899,3000 3920,3000 3975,2945 3975,2920 4005,2890 v1(4030,2890) 4033,2887 CA48.1@4033,2862 4033,2778.8 ; CA59.1@3901.42,3002 3901,3002 3862,3002 3843.77,3002 v1@3830,2988.23 ; v1(4183,2542) 4239,2598 4239,2698.88 4179.74,2758.14 4053.66,2758.14 ; 3605,2750 3649.47,2705.53 4023,2705.53 4033,2715.53 4033,2748.35 ; 4033,2748.35 4042.79,2758.14 4053.66,2758.14 ; 4033,2748.35 4033,2778.8 ; 4033,2778.8 4053.66,2758.14
BBPLL_V12A: C36.1 R23.2 U1.A7 | length 105
  Top w10: U1.A7@2331.07,2272.45 2341,2282.38 v2(2341,2286)
  Bottom w10: R23.2@2347.86,2335.86 R23.2@2348.02,2336.02
  Bottom w15: v2(2341,2286) 2349,2294 2349,2336.73 R23.2@2348.86,2336.86
  Bottom w20: R23.2@2348.02,2336.02 R23.2@2348.73,2336.73 2348.86,2336.86 C36.1@2371.27,2359.27
BG_RES_12K: C83.1 R107.1 U1.A4 | length 389.3
  Top w5: U1.A4@2276.79,2326.74 2279.74,2326.74 2291.7,2338.7 2291.7,2355.7 2300,2364 2315,2364 2384,2433 2409,2433 2467,2491 C83.1@2492,2491 ; C83.1@2492.77,2491.77 C83.1@2492,2491 ; R107.1@2570,2532 2553,2515 2552.75,2515 2528.75,2491 C83.1@2492,2491
CAP1: C111.1 U12.3 | length 78
  Top w20: U12.3@2364,1199 2367,1199 C111.1@2367,1274
CAP2: C114.1 U14.3 | length 73
  Top w20: C114.1@1356,1269 1356,1199 U14.3@1359,1199
CAP3: C121.1 U16.4 | length 87.8
  Top w5: U16.4@3067,1204 3069,1202 U16.4@3069,1194
  Top w20: C121.1@3067,1264 3067,1204 3067,1189 U16.4@3069,1189
CAP4: C115.1 U14.8 | length 73
  Top w20: C115.1@856,1269 856,1199 U14.8@859,1199
CAP5: C112.1 U12.8 | length 72
  Top w20: U12.8@1864,1199 1866,1199 C112.1@1866,1269
CHGND: C113.2 C116.2 C117.2 C118.2 C119.2 C120.2 C122.2 C123.2 | length 1598.6
  Top w20: v1(542,830) 542,769 C113.2@548,769 ; v1(548,720) C113.2@548,769 ; C113.2@548.88,769 C113.2@548,769 ; v1(3518,802) 3518,754 C123.2@3519.12,754 3520,754 v1(3520,706) ; v1(3534,664) 3536,662 v1(3536,568)
  Bottom w20: C117.2@523.37,486 C117.2@539.12,486 ; C117.2@523.37,520 C117.2@538,520 ; C120.2@533.37,202 C120.2@544,202 ; C120.2@533.37,238 C120.2@542,238 ; v1(538,556) C117.2@538,520 ; v1(542,268) C120.2@542,238 ; v1(542,452) C117.2@542,486 ; v1(542,830) 542,789.6 526.4,774 C116.2@544.12,774 548,774 v1(548,720) ; v1(544,170) C120.2@544,202 ; v1(572,486) C117.2@542,486 ; v1(572,520) C117.2@539.12,520 ; v1(584,202) C120.2@549.12,202 ; v1(584,238) C120.2@549.12,238 ; v1(3496,598) 3524,598 3528,602 3528,612.12 C122.2@3531.88,616 ; v1(3498,638) 3524,638 3531.88,630.12 C122.2@3531.88,616 ; v1(3502.59,212.66) C118.2@3537.37,212.66 ; v1(3505,395) C119.2@3538.88,395 ; v1(3505,425) C119.2@3535,425 ; v1(3505.67,176.9) C118.2@3531.61,176.9 ; v1(3531.61,146.64) C118.2@3531.61,176.9 ; v1(3534,664) C122.2@3534,613.88 ; v1(3535,460) C119.2@3535,425 ; C119.2@3535.88,412 C119.2@3538.88,409 ; v1(3536,568) 3536,611.88 C122.2@3534,613.88 ; v1(3537.37,254.01) C118.2@3537.37,212.66 ; v1(3540,360) C119.2@3540,395 ; C118.2@3553.11,176.9 C118.2@3537.37,176.9 ; C118.2@3553.11,212.66 C118.2@3537.37,212.66 ; C119.2@3554.63,395 C119.2@3540,395 ; C119.2@3554.63,425 C119.2@3538.88,425 ; C117.2@538,520 C117.2@539.12,520 ; C117.2@538,520 538,504 C117.2@539.12,504 ; C117.2@539.12,486 C117.2@542,486 ; C117.2@539.12,486 C117.2@539.12,504 ; C117.2@539.12,504 542,504 C117.2@542,486 ; C117.2@539.12,504 C117.2@539.12,520 ; C120.2@542,238 542,219 C120.2@544,219 ; C120.2@542,238 C120.2@549.12,238 ; C120.2@544,202 C120.2@544,219 ; C120.2@544,202 C120.2@549.12,202 ; C120.2@544,219 C120.2@549.12,219 ; C120.2@549.12,202 C120.2@549.12,219 ; C120.2@549.12,219 C120.2@549.12,238 ; C118.2@3531.61,176.9 C118.2@3537.37,176.9 ; C118.2@3531.61,176.9 3531.61,194.11 C118.2@3537.37,194.11 ; C122.2@3531.88,616 C122.2@3534,613.88 ; C119.2@3535,425 C119.2@3538.88,425 ; C119.2@3535,425 3535,409 C119.2@3538.88,409 ; C118.2@3537.37,176.9 C118.2@3537.37,194.11 ; C118.2@3537.37,194.11 C118.2@3537.37,212.66 ; C119.2@3538.88,395 C119.2@3540,395 ; C119.2@3538.88,395 C119.2@3538.88,409 ; C119.2@3538.88,409 C119.2@3538.88,425 ; C119.2@3538.88,409 3540,409 C119.2@3540,395
  other v1: 848,135 1023,135 1198,135 1398,135 1648,135 1823,135 2048,135 2198,135 2373,135 2523,135 2673,135 2798,135 2948,135 3073,135 3198,135 3323,135 3448,135 1866.3,233.88 2552.04,233.88 3306.56,236.28 1548.83,237.06 3151.4,243.16 2115.52,246.58 1153.58,249.76 2332.99,264.04 878.96,330.71 1098,360 1373,360 1673,360 1973,360 2223,360 2448,360 2598,360 3123,360 3273,360 1791.7,403.73 1517.08,408.49 2521.88,414.84 2096.47,422.78 2348.86,422.78 2759.99,422.78 3001.15,428.76 3193.63,430.72 1271.04,435.48 3395.93,446.44 847,499 1527,507 1977,507 3277,507 1148,510 1773,510 2223,510 2373,510 2673,510 2898,510 3098,510 3448,510 3436.69,835.39 575,842 3442.94,902.77 3362.78,987.26 727.72,998.7 1934.72,1035.82 3131.52,1036.2 1562.57,1037.02 2294.55,1037.15 2446.11,1037.15 2696.68,1036.74 3276.49,1037.28 1381.52,1037.77 2792.76,1038.47 817.98,1038.58 1052.03,1038.58 1220.75,1039.27 1673.01,1038.52 1824.22,1039.19 2115.45,1039.12 2943.26,1039.44 2594.12,1046.69
CLK_A_IN: C1061.2 CA76.2 R810.1 | length 428.6
  Top w5: R810.1@3113.5,2483 C1061.2@3113.5,2450 3167.58,2395.92 3262.08,2395.92 3355,2488.84 CA76.2@3355,2582
CLK_N: C127.2 R100.2 R150.2 U22.K8 | length 314.8
  Top w4.5: U22.K8@1334.54,2087.83 1349.92,2103.2 1419.2,2103.2 1468.5,2152.5 1530.5,2152.5 C127.2@1543.5,2139.5
  Top w5: C127.2@1543.5,2139.5 R150.2@1578.86,2139.5 1578.86,2140.5 1614.15,2140.5 1614.39,2140.74 1614.89,2141.24 R100.2@1613.89,2141.24
CLK_P: C127.1 R99.2 R150.1 U22.J8 | length 308
  Top w4.5: U22.J8@1334.54,2119.32 1344.61,2119.32 1361.29,2136 1436.85,2136 1463.66,2162.47 1530.47,2162.47 C127.1@1543.5,2175.5
  Top w5: C127.1@1543.5,2175.5 1577.86,2175.5 R150.1@1578.86,2174.5 ; R150.1@1578.86,2175.5 R150.1@1578.86,2174.5 ; R99.2@1613.89,2176.59 1614.89,2176.59 1614.89,2174.5 R150.1@1578.86,2174.5
CMT0: R118.2 U14.13 | length 77
  Top w20: R118.2@854,827 854,899 U14.13@859,899
CMT1: R115.2 U14.18 | length 72
  Top w20: R115.2@1359,827 U14.18@1359,899
CMT2: R112.2 U12.13 | length 72
  Top w20: R112.2@1864,827 U12.13@1864,899
CMT3: R109.2 U12.18 | length 72
  Top w20: R109.2@2364,827 U12.18@2364,899
CMT4: R121.2 U16.13 | length 78.7
  Top w5: U16.13@3065,890 U16.13@3069,894
  Top w20: U16.13@3060,890 U16.13@3065,890 ; R121.2@3065,823 U16.13@3065,890 ; U16.13@3066,890 U16.13@3065,890
CPURST_N: R899.2 U1.C6 | length 6263.5
  Top w5: v2(2276.54,2237.97) 2276.66,2237.97 2276.66,2254.36 U1.C6@2276.79,2254.36
  Inner Layer 3 w4: v2(2276.54,2237.97) 2294,2220.51 2294,2197.2 2305.2,2186 2321.37,2186 2360.37,2225 2375,2225 2380,2230
  Inner Layer 3 w5: 2380,2230 2415,2265 3100,2265 3195,2360 3195,3423.06 3086.06,3532 2920,3532 v1(2906,3518)
  Bottom w5: R899.2@352,2220 399,2220 664,2485 664,3314 1139,3789 1564,3789 1599,3754 2698,3754 2906,3546 v1(2906,3518)
D1: L4.1 U6.4 U6.6 | length 334
  Bottom w20: U6.6@2862.18,2082.6 L4.1@2945.5,2082.6 ; U6.4@2862.18,2157.4 2947.01,2157.4 L4.1@2947.01,2130 ; L4.1@2929.91,2112.9 L4.1@2945.5,2128.49 ; L4.1@2945.5,2063.1 L4.1@2945.5,2082.6 ; L4.1@2945.5,2082.6 2947.01,2082.6 L4.1@2947.01,2130 ; L4.1@2945.5,2082.6 L4.1@2945.5,2128.49 ; L4.1@2945.5,2128.49 L4.1@2947.01,2130
DCDC_V33A: C54.1 R28.2 U1.B16 | length 246.6
  Top w5: U1.B16@2475.83,2091.5 2493.93,2091.5 2515.43,2070 C54.1@2607,2070 2627,2090 2677,2090 R28.2@2697,2070
DCDC_V33D: C29.1 C30.1 C51.1 R27.2 U1.A14 U6.2 | length 422.9
  Top w10: U1.A14@2457.74,2145.79 2480.62,2168.67 2535.34,2168.67 v1(2540.74,2163.26)
  Bottom w10: v1(2540.74,2163.26) 2588.42,2115.59 C30.1@2631.43,2115.59 ; C30.1@2635,2118 C29.1@2690,2118 2690,2120 U6.2@2759.82,2120
  Bottom w20: C30.1@2635,2118 C30.1@2635,2115.59 2631.43,2115.59 2631.43,2141.93 R27.2@2648.5,2159 2681,2159 C51.1@2681,2157
DDR_BA0: R97.2 U22.L2 | length 766.7
  Top w4.5: v2(1130.8,2041.8) 1144.8,2056.33 U22.L2@1145.57,2056.33
  Bottom w4.5: v2(1130.8,2041.8) 1146.1,2026.5 1168.5,2026.5 1227.5,1967.5 1227.5,1913.5 1416,1725 1611,1725 1622.5,1736.5 1705.5,1736.5 1706.5,1735.5 R97.2@1706.5,1733.5
DDR_BA1: R98.2 U22.L3 | length 642.4
  Top w4.5: v2(1162.1,2041.8) U22.L3@1177.06,2056.33
  Bottom w4.5: v2(1162.1,2041.8) 1168.5,2041.8 1237.8,1972.5 1237.8,1918.2 1384.5,1771.5 1638.5,1771.5 R98.2@1639.5,1772.5
DDR_BA2: R827.2 U22.L1 | length 808.6
  Top w4.5: v1(1099.42,2042.77) 1099.69,2042.5 1113.8,2056.6 U22.L1@1114.07,2056.33
  Bottom w4.5: v1(1099.42,2042.77) 1112.5,2029.69 1112.5,1913.5 1424.5,1601.5 R827.2@1636.5,1601.5
DDR_CASN: R104.2 U22.L7 | length 266.1
  Top w4.5: U22.L7@1303.05,2056.33 1314.5,2044.88 1314.5,2044.5 v2(1316.5,2042.5)
  Bottom w4.5: v2(1316.5,2042.5) 1333.25,2025.75 1353.25,2025.75 1353.5,2025.5 1360.5,2025.5 1371.5,2014.5 1459.5,2014.5 1460.5,2015.5 1529.5,2015.5 1530.5,2014.5 1546.5,2014.5 R104.2@1549.5,2017.5
DDR_CLK_N: R100.1 U1.P2 | length 372.4
  Top w4.5: R100.1@1649.89,2141.24 1648.89,2141.24 1660.15,2152.5 1962.5,2152.5 1986.31,2128.69 2004.36,2128.69 U1.P2@2005.36,2127.69
DDR_CLK_P: R99.1 U1.P1 | length 351.1
  Top w4.5: R99.1@1649.89,2176.59 1649.41,2176.59 1663.5,2162.5 1970.55,2162.5 U1.P1@1987.26,2145.79
DDR_CSN: R106.2 U22.L8 | length 153.3
  Top w4.5: U22.L8@1334.54,2056.33 1349.33,2056.33 1349.5,2056.5 1364.74,2056.5 v2(1364.74,2057.54)
  Bottom w4.5: v2(1364.74,2057.54) 1364.74,2057.74 v2@1365.5,2058.5
  Bottom w5: v2@1365.5,2058.5 1472.5,2058.5 1481.5,2049.5 R106.2@1480.5,2049.5
DDR_IO_VREF: C70.1 C820.2 C821.1 R812.2 R813.1 U1.L5 | length 529.7
  Top w5: v2(2096,2127.5) U1.L5@2113.93,2127.69
  Bottom w8: R812.2@1744,2254 C820.2@1779,2254 1829,2254 C821.1@1832,2251 1832.5,2251.5 C70.1@1865.5,2251.5 1899.5,2251.5 R813.1@1901.5,2253.5 1901.5,2252.5 2072.5,2252.5 2131.5,2193.5 2131.5,2136 2124,2128.5 2097,2128.5 v2(2096,2127.5)
DDR_MCKE: R101.2 U22.K2 | length 755.4
  Top w4.5: v2(1126.5,2078.5) 1130.17,2078.5 1131.17,2077.5 1141.5,2087.83 U22.K2@1145.57,2087.83
  Bottom w4.5: v2(1126.5,2078.5) 1146.5,2058.5 1167.5,2058.5 1248.5,1977.5 1248.5,1922.5 1378.5,1792.5 R101.2@1707.5,1792.5
DDR_MDQM0: R95.2 U22.F3 | length 1127.3
  Top w4.5: v2(1161.5,2103.3) 1181.6,2103.3 1193.5,2091.4 1193.5,1850.5 1280.5,1763.5 1644.5,1763.5 1778.5,1897.5 1778.5,1904.64 R95.2@1778.17,1904.31 ; U22.F3@1177.06,2213.81 1177.65,2214.4 v2(1197.4,2214.4)
  Bottom w4.5: v2(1161.5,2103.3) 1163,2103.3 1179,2119.3 1179,2138.8 1216,2175.8 1216,2200 1201.6,2214.4 v2(1197.4,2214.4)
DDR_MDQM1: R96.2 U22.B3 | length 694.8
  Top w4.5: U22.B3@1177.06,2339.8 1177.06,2340.5 v2(1203.5,2340.5) ; v1(1376.5,2414.5) 1521.5,2414.5 1728.5,2207.5 R96.2@1748.5,2207.5 R96.2@1749.5,2207.5
  Bottom w4.5: v2(1203.5,2340.5) 1217.15,2354.15 1325.15,2354.15 1376.5,2405.5 v1(1376.5,2414.5)
DDR_MDQS0: R93.2 U22.F7 | length 1177.7
  Top w4.5: v2(1196.7,2130.5) 1204.5,2121.5 1204.5,1855.5 1286.5,1773.5 1639.5,1773.5 1750.5,1884.5 1750.5,1904.93 R93.2@1817.06,1971.49 ; v2(1248.5,2212.5) 1248.5,2213.81 U22.F7@1303.05,2213.81
  Bottom w4.5: v2(1196.7,2130.5) 1197.1,2130.9 1197.1,2132.1 1248.5,2183.5 v2(1248.5,2212.5)
DDR_MDQS1: R94.2 U22.B7 | length 755.5
  Top w4.5: U22.B7@1303.05,2339.8 1271.5,2371.34 1271.5,2414.57 v1(1317.6,2460.68) ; v1(1399,2450.2) 1423.2,2426 1527,2426 1725.5,2227.5 R94.2@1823.5,2227.5
  Bottom w4.5: v1(1317.6,2460.68) 1388.52,2460.68 v1(1399,2450.2)
DDR_MODT: R479.2 U22.K9 | length 116.8
  Top w4.5: U22.K9@1366.04,2087.83 1388.17,2087.83 v2(1388.5,2087.5)
  Bottom w4: v2(1388.5,2087.5) 1478.5,2087.5 1479.5,2088.5 R479.2@1481.5,2086.5
DDR_RASN: R103.2 U22.K7 | length 270.7
  Top w4.5: U22.K7@1303.05,2087.83 1316.5,2074.37 v2(1316.5,2072.5)
  Bottom w4.5: v2(1316.5,2072.5) 1332.5,2088.5 1359.83,2088.5 1376.83,2071.5
  Bottom w5: 1376.83,2071.5 1458.83,2071.5 1461.83,2068.5 1541.5,2068.5 R103.2@1548.5,2075.5
DDR_VREF: C124.2 C125.1 R350.2 R351.1 U22.J2 | length 271.5
  Top w4.5: R351.1@1001.5,2100.5 R351.1@1002.6,2100.5
  Top w8: C124.2@891.5,2099.5 891.5,2101.5 R350.2@926.5,2101.5 ; R350.2@926.5,2099.5 R350.2@926.5,2101.5 ; C125.1@961.5,2099.5 C125.1@961.5,2101.5 ; R351.1@1001.5,2099.5 1002.6,2100.5 R351.1@1003.1,2100.5 ; U22.J2@1145.57,2119.32 1145.39,2119.5 1139.5,2119.5 1120.5,2100.5 R351.1@1003.1,2100.5 ; R350.2@926.5,2101.5 C125.1@961.5,2101.5 ; C125.1@961.5,2101.5 1002.1,2101.5 R351.1@1003.1,2100.5
DDR_WEN: R105.2 U22.K3 | length 639.3
  Top w4.5: v2(1162.6,2073.8) U22.K3@1177.06,2087.83
  Bottom w4.5: v2(1162.6,2073.8) 1162.6,2072.5 1168.5,2072.5 1258.5,1982.5 1258.5,1927.5 1373.5,1812.5 R105.2@1640.5,1812.5
DINT: J13.13 R471.2 | length 85.8
  Top w5: J13.13@1689,3209 1691,3207 R471.2@1691,3124
DVDD_1V2_IN: CA68.1 CA71.1 CA72.1 CA73.1 RA19.2 UA4.19 UA4.35 UA4.36 UA4.42 | length 1668.5
  Top w5: 3931.62,2537.88 3931.62,2529 3931.62,2522.81 CA68.1@3932.54,2522.81
  Top w8: CA71.1@3568,2607 3569,2607 CA71.1@3569,2606 ; 3601.77,2631.75 3602.29,2632.27 UA4.19@3623.8,2632.27 ; UA4.35@3893.49,2598.8 3893.49,2579.57 3898.7,2574.36 3903.7,2574.36 3909.24,2579.9 UA4.36@3909.24,2598.8 ; UA4.42@3974.2,2679.51 4011.42,2679.51 4023.68,2691.77
  Top w12: 4023.68,2691.77 4052.26,2720.35 4054.68,2720.35 4054.68,2718.19 4054.68,2718.06 CA73.1@4054.68,2717.93
  Top w15: CA71.1@3569,2605.16 3569.84,2605.16 3595.01,2630.32 3595.01,2631.75 3601.77,2631.75 ; 3903.7,2574.36 3910.78,2567.28 3910.78,2558.72 3931.62,2537.88 ; CA73.1@4054.68,2718.06 4054.55,2718.06 4054.68,2718.19 4075.92,2739.43 4148.65,2739.43 4169.81,2718.27 v1(4169.95,2718.41)
  Top w20: v1(3568.13,2583.93) 3569,2583.93 3569,2605.16 CA71.1@3569,2606 ; v1(3903,2530) 3903,2529 3931.62,2529 3932.54,2529 CA68.1@3932.54,2522.81
  Bottom w5: RA19.2@3763,2354 RA19.2@3763,2360 ; CA72.1@3935,2530 CA72.1@3937,2528
  Bottom w20: v1(3568.13,2583.93) 3568.13,2530.5 3555,2517.37 3555,2433.63 3634.63,2354 3763,2354 3875.45,2354 3913,2391.55 3913,2507.21 ; CA72.1@3939,2528 3937,2528 3933.79,2528 3913,2507.21 ; v1(4169.95,2718.41) 4186.55,2701.81 4186.55,2602.61 4113.94,2530 3935,2530 v1(3903,2530) 3913,2520 3913,2507.21
DVDD_PCIE_1V2_IN: CA61.1 CA62.1 RA19.1 UA4.28 | length 245.2
  Top w8: CA62.1@3779.26,2535.93 3779.26,2567.64 3783.46,2571.84 3783.25,2572.04 UA4.28@3783.25,2598.8 3784.19,2597.87 3784.19,2576.57
  Top w15: v1(3758.43,2520.32) 3760.2,2518.54 3778.43,2536.77 3778.43,2535.93 CA62.1@3779.26,2535.93
  Bottom w15: v1(3758.43,2520.32) 3758.43,2452.57 CA61.1@3765,2446 3763,2444 RA19.1@3763,2396
DVDD_PCIE_3V3_IN: CA67.1 CA69.1 CA70.1 RA18.1 UA4.21 UA4.25 | length 378.5
  Top w8: 3648.1,2563.07 3652.37,2563.07 3673.02,2583.71 UA4.21@3673.02,2598.8 ; 3735.61,2576.32 3735.61,2598.8 UA4.25@3736.01,2598.8
  Top w12: RA18.1@3553,2510 3553,2507 3570,2524 CA67.1@3587,2524 ; CA70.1@3711,2538 3711,2551.71 v1@3723.09,2563.8 ; v1(3726.16,2560.73) v1@3723.09,2563.8 ; 3735.61,2576.32 v1@3723.09,2563.8
  Top w15: CA69.1@3619,2524 3619.18,2524 v1(3619.18,2550.02) 3632.23,2563.07 3648.1,2563.07
  Top w16: CA67.1@3587,2524 CA69.1@3619,2524
  Bottom w5: v1@3720.21,2560.91 3726.16,2560.91 v1(3726.16,2560.73) 3720.39,2560.73 v1@3720.21,2560.91
  Bottom w12: v1(3619.18,2550.02) 3630.07,2560.91 v1@3720.21,2560.91
EJTAG-TDO: J13.5 R475.2 R478.1 | length 128
  Top w5: R478.1@1254,3122 R475.2@1289,3122 ; J13.5@1289,3209 R475.2@1289,3122 ; R475.2@1295,3122 R475.2@1289,3122
EPHT_REF_RES: R42.2 U1.R15 | length 79.1
  Top w5: v2(2206,1874.5) 2206.14,1874.36 U1.R15@2222.5,1874.36
  Bottom w5: R42.2@2201,1814 2202,1815 2202,1870.5 v2(2206,1874.5)
EPHY_PLL_V12A: R55.2 U1.M13 | length 52
  Top w8: v2(2240.5,1947.5) 2240.5,1964.74 U1.M13@2240.6,1964.83
  Bottom w8: v2(2240.5,1947.5) 2242.78,1949.78 2242.78,1980.18 R55.2@2242.07,1979.47
EPHY_V33A: C57.1 C58.1 R29.2 U1.N12 U1.N13 | length 367.6
  Top w8: U1.N12@2204.4,1964.83 2213.5,1964.83 2222.5,1955.83 U1.N13@2222.5,1946.74 v2(2222.5,1930)
  Bottom w12: C58.1@2122.27,1725.73 2118.93,1729.07 2165,1775.14 2165,1880 2195.73,1910.73 2203.23,1910.73 v2(2222.5,1930)
  Bottom w15: C57.1@2121.73,1679.73 2099.43,1702.02 2098.02,1702.02 R29.2@2098.73,1702.73 2121.73,1725.73 C58.1@2122.27,1725.73
EXT_LDO_DIG: U1.B17 U8.1 | length 613
  Top w5: U1.B17@2493.93,2073.4 2515.33,2052 v1(2576,2052)
  Bottom w5: v1(2576,2052) 2576,2032.76 2660.36,1948.4 2781.6,1948.4 2960,1770 U8.1@2960,1760
FB: R894.2 R898.1 U626.1 | length 100
  Top w20: R894.2@988,2915 R898.1@1022,2915 1022,2852.43 U626.1@1019.55,2849.98
G0_INVT: R932.2 U632.2 | length 40.1
  Top w5: U632.2@1779,2627.72 1779,2606.47 1780,2605.47 R932.2@1780,2588
G1: U1.B14 U6.1 | length 428.2
  Top w5: U1.B14@2439.64,2127.69 2457.76,2127.67 2470.14,2115.28 2481.52,2115.28 2488.24,2122 2551.73,2122 2561.41,2112.32 2797.32,2112.32 v1(2800,2115)
  Bottom w5: U6.1@2759.82,2082.6 2769.66,2082.6 2800,2112.94 v1(2800,2115)
G2: U1.A15 U6.3 | length 384.8
  Top w5: U1.A15@2475.83,2127.69 2479.24,2131.1 2556.02,2131.1 2565.8,2121.32 2781.32,2121.32 v1(2800,2140)
  Bottom w5: U6.3@2759.82,2157.4 2782.6,2157.4 v1(2800,2140)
